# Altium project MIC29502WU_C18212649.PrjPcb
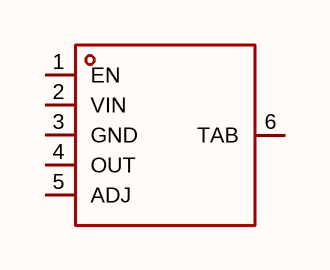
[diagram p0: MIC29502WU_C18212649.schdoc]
1 sheet, 1 parts. Net scope: global (net labels, ports and power ports of the same name join across sheets).

## Sheet MIC29502WU_C18212649.schdoc
size 127 x 101 mm

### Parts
U?  mic29502wu_c18212649  [TO-263-5_L10.2-W9.9-P1.70-LS14.4-TL]  (value not drawn)

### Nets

Not connected (* = marked no-connect by the designer): U? 1(EN) 2(VIN) 3(GND) 4(OUT) 5(ADJ) 6(TAB)

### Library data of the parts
U? = mic29502wu_c18212649: 输出极性:正极;工作电压:26V;输出电压:1.24V~15V;输出电流:5A;电源纹波抑制比(PSRR):-;输出类型:可调;; Manufacturer: TECH PUBLIC(台舟); AddInBom: yes; ModelId: 4e421a816a7f4d57b8710832ddea550a; ModelName: TO-263-5-5P_L10.2-W8.7-H4.5-LS14.4-P1.70; ModelTransform: 401.574,560.17797,0,270,0,0,38.773,0.078,0; Output Configuration: 正极; Voltage - Supply: 26V; Output Current: 5A; Voltage Dropout: 560mV@(5A); standby current: 60mA; Noise: 400uVrms; Output Type: 可调; Number of Outputs: 1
